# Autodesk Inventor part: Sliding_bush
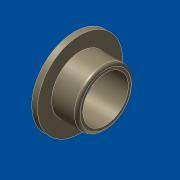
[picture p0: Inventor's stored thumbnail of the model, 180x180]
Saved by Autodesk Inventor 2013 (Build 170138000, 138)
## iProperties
Shininess: 41.0
Length Units: 11269
Angle Units: 11279
Time Units: 11290
Mass Units: 11283
Length Display Precision: 3
Angle Display Precision: 2
Created: 2001-04
Part Number: Sliding_bush
Material: Standard
Document SubType Name: Modellieren
Designer: dl
Density: 1 g/cm^3
Density: 0.0
Volumn: 0.0
Area: 0.0
PropertySet Name: Model Information
Control State: 0
Master: False
Checked Out: False
Author: dl
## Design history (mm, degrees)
body "Solid1"
sketch "Sketch2"
  geometry: C1 r 7.5 at (0, 0) reference; 1 further point
  constraints: 1 coincident
revolve "Revolution1" stored, may be unused: angle "d4" = 90 deg
hole "Hole1" sketch "Sketch2" diameter "d5" = 8; stored, may be unused: countersink angle "d9" = 60 deg, drill point angle "d11" = 118 deg; dims "d6" = 6, "d7" = 4, "d8" = 2, "d10" = 8
fillet "Fillet1" dims "d12" = 0.5
sketch "Sketch1"
  geometry: L1 (0, 0)-(0, 7.5); L2 (0, 7.5)-(1, 7.5); L3 (1, 7.5)-(1, 5); L4 (1, 5)-(5.5, 5); L5 (5.5, 5)-(5.5, 0); L6 (5.5, 0)-(0, 0)
  constraints: 12 end point, 4 parallel, 1 perpendicular, 1 vertical
  dimensions: "d0" = 7.5 distance of L1.start L1.end; "d1" = 5 distance of L4.end L5.end; "d2" = 4.5 distance of L3.end L4.end; "d3" = 5.5 distance of L5.end L1.start
